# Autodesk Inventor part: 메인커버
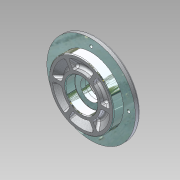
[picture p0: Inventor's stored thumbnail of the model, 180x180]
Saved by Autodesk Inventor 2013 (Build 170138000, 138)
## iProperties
Manager: KYOUNG IL JANG
Company: 한국ATC센터
Created: 2012-10
Part Number: 메인커버
Document SubType Name: Modeling
Density: 1 g/cm^3
Checked By: KYOUNG IL JANG
Vendor: CBT Solutions
Designer: KYOUNG IL JANG
Material: 일반
Author: KYOUNG IL JANG
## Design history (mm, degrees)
sketch "스케치1"
  geometry: L1 (0, 0)-(0, 28.5); L2 (0, 0)-(28.5, 0); L3 (28.5, 0)-(28.5, 4.726); L4 (28.5, 8)-(31.774, 8); L5 (32.966, 8)-(33.879, 7.234); L6 (42.5, 0)-(47.5, 0); L7 (47.5, 0)-(47.5, 14.5); L8 (47.5, 14.5)-(65, 14.5); L9 (65, 14.5)-(65, 22.5); L10 (65, 22.5)-(33.464, 22.5); L11 (33.464, 22.5)-(30, 28.5); L12 (30, 28.5)-(0, 28.5); L13 (28.5, 4.726)-(28.5, 8); L14 (31.774, 8)-(32.966, 8); L15 (33.879, 7.234)-(42.5, 0); L16 (23.5, 0)-(23.5, 14); L17 (23.5, 14)-(15, 14); L18 (15, 14)-(15, 20.5); L19 (15, 20.5)-(17.5, 20.5); L20 (17.5, 20.5)-(17.5, 28.5); A1 r 3.274 centre (31.774, 4.726) between (33.879, 7.234) and (28.5, 4.726)
  constraints: 40 end point, 11 parallel, 6 perpendicular, 6 tangent, 3 point on circle, 2 collinear, 2 point on line, 1 centre point, 1 vertical
  dimensions: "d1" = 130 diameter of L9 L1; "d2" = 95 diameter of L7 L1; "d3" = 57 diameter of L3 L1; "d4" = 5 distance of L6.start L6.end; "d5" = 14.5 distance between parallel lines of L8 L6; "d6" = 8 distance of L8.end L9.end; "d7" = 6 distance between parallel lines of L10 L12; "d8" = 8 distance of L2.end L4.start; "d9" = 140 deg angle of L6 L5; "d10" = 47 diameter of L16 L1; "d11" = 14 distance of L16.start L16.end; "d12" = 35 diameter of L20 L1; "d13" = 8 distance of L19.end L20.end; "d14" = 30 diameter of L18 L1; "d15" = 120 deg angle of L10 L11; "d16" = 60 diameter of L11.end L1
revolve "회전1" sketch "스케치1" stored, may be unused: angle "d17" = 90 deg
sketch "스케치2"
  geometry: L1 (28.5, 0)-(42.5, 0); 3 further points
  constraints: 2 end point, 2 horizontal alignment, 1 horizontal, 1 point on line, 2 other
feature "리브1" sketch "스케치2" dims "d18" = 5, "d19" = 1, "d20" = 0
fillet "모깎기1" dims "d21" = 3
fillet "모깎기2" dims "d25" = 3, "d26" = 0.3
chamfer "모따기1" distance "d27" = 1; stored, may be unused: second distance "d28" = 2, angle "d29" = 45 deg
sketch "스케치3"
  geometry: C1 r 2.067 at (55, 0) reference; C2 r 2.067 at (0, -55) reference; C3 r 2.067 at (-55, 0) reference; C4 r 2.067 at (0, 55) reference; 1 further point
hole "구멍1" sketch "스케치3" at (0, 55), (-55, 0), (0, -55), (55, 0) diameter "d30" = 4.5; stored, may be unused: countersink angle "d34" = 90 deg, drill point angle "d36" = 118 deg; dims "d31" = 6, "d32" = 8, "d33" = 4.4, "d35" = 8
node "솔리드1"
pattern_circular "원형 패턴1" dims angle "d23" = 360 deg
node "참조1"
node "참조2"
node "참조3"
node "참조4"
